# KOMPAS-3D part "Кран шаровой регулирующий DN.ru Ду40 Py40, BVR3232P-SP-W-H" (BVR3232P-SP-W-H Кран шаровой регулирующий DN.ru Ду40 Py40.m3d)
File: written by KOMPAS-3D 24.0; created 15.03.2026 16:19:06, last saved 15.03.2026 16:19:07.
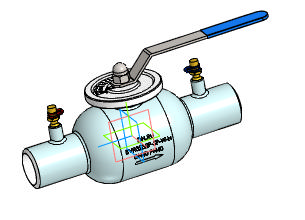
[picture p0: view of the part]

Document properties: Автор: Максим; Полное имя файла: D:\Rabota ebanaya\BVR3232P-SP-W-H Кран шаровой регулирующий Ду15-150\Типоразмеры\DN40\BVR3232P-SP-W-H Кран шаровой регулирующий DN.ru Ду40 Py40.m3d

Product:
- Body: Тело 1  | qty 1
    Масса: 6.460664
- Part/product: Кран шаровой регулирующий DN.ru Ду40 Py40  | designation BVR3232P-SP-W-H
    Масса: 4.4
    Раздел спецификации: Прочие изделия
    Примечание: D160-69410

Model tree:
1. Операция без истории:1

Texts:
  BVR3232P-SP-W-H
